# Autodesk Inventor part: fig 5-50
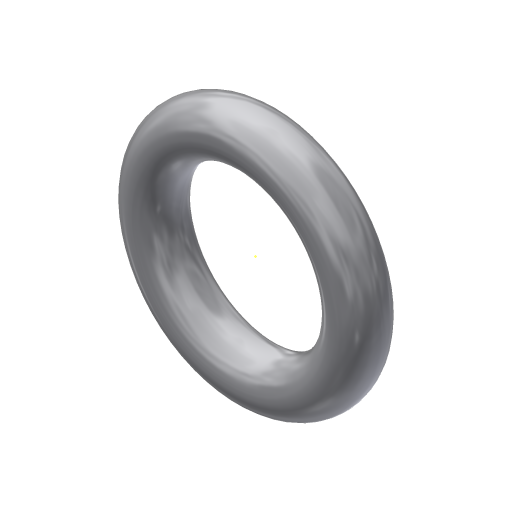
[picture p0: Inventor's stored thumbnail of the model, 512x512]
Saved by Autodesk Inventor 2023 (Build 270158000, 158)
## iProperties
Created: 2010-02
Part Number: fig 5-50
Document SubType Name: Modeling
Designer: CADSoft
Density: 1 g/cm^3
Material: Generic
Appearance: Default
Author: CADSoft
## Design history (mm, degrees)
sketch "Sketch1"
  geometry: L1 (0, 21.37)-(0, -16.247); C1 r 5 at (20.026, 0); 1 further point
  constraints: 2 end point, 1 centre point
  dimensions: "d0" = 10 diameter of C1
revolve "Revolution1" sketch "Sketch1" stored, may be unused: angle "d1" = 90 deg
workpoint "Work Point1"
body "Solid1"
